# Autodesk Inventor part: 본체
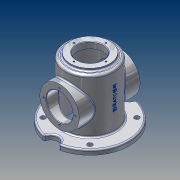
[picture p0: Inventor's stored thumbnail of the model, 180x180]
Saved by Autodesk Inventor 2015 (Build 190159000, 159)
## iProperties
Created: 2018-04
Part Number: 본체
Material: 알루미늄 6061
Document SubType Name: Modeling
Designer: user
Density: 2.7 g/cm^3
Appearance: 알루미늄 - 평지
Mass: 1147.05 g
Surface Area: 1200.36 cm^2
Volume: 424.833 cm^3
Author: user
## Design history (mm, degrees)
sketch "스케치1"
  geometry: L1 (0, 65)-(0, -60); L2 (-40, 65)-(-40, 60); L3 (-40, 60)-(-45, 60); L4 (-50, 55)-(-50, -47); L5 (-53, -50)-(-80, -50); L6 (-80, -50)-(-80, -60); L7 (-80, -60)-(-45, -60); L8 (-40, 65)-(-27, 65); L9 (-27, 65)-(-27, 52); L10 (-27, 52)-(-42, 52); L11 (-45, 49)-(-45, -60); A1 r 5 centre (-45, 55) between (-45, 60) and (-50, 55); A2 r 3 centre (-42, 49) between (-42, 52) and (-45, 49); A3 r 3 centre (-53, -47) between (-53, -50) and (-50, -47); 5 further points
  constraints: 22 end point, 7 perpendicular, 6 point on circle, 6 point on line, 6 tangent, 3 centre point, 2 horizontal alignment, 2 vertical, 1 horizontal, 1 midpoint, 1 vertical alignment
  dimensions: "d0" = 125 distance of L1.start L1.end; "d1" = 60 distance of point (0, 0) L1.end; "d2" = 54 diameter of L9 L1; "d3" = 80 diameter of L2 L1; "d4" = 10 distance between parallel lines of L7 L5; "d5" = 160 diameter of L6 L1; "d6" = 13 distance between parallel lines of L8 L10; "d7" = 110 distance between parallel lines of L5 L3; "d8" = 100 diameter of L4 L1; "d9" = 90 diameter of L11 L1; "d14" = 5 radius of A1; "d15" = 3 radius of A2; "d16" = 3 radius of A3
revolve "회전1" sketch "스케치1" stored, may be unused: angle "d10" = 90 deg
sketch "스케치2"
  geometry: C1 r 45 at (0, 0) reference; C2 r 80 at (0, 0) reference; C3 r 50 at (0, 0)
  constraints: 1 centre point, 1 coincident
  dimensions: "d11" = 100 diameter of C3
extrude "돌출1" join sketch "스케치2" distance "d12" = 8; taper "d13" = 0 deg
node "작업 평면1"
sketch "스케치3"
  geometry: C1 r 40 at (0, 0); C2 r 27 at (0, 0); 2 further points
  constraints: 2 centre point, 2 coincident, 1 vertical alignment
  dimensions: "d18" = 80 diameter of C1; "d19" = 54 diameter of C2; "d24" = 32.5 distance of point (0, 0) point (0, 32.5)
extrude "돌출2" join sketch "스케치3" stored distance "d20" = 8; taper "d21" = 0 deg
extrude "돌출3" cut sketch "스케치3" stored distance "d22" = 8; taper "d23" = 0 deg
hole "구멍1" sketch "스케치3" diameter "d25" = 3.242; stored, may be unused: countersink angle "d29" = 90 deg, drill point angle "d31" = 118 deg; dims "d26" = 8, "d27" = 4, "d28" = 2, "d30" = 10
sketch "스케치4"
  geometry: C1 r 40 at (0, 0) reference; 1 further point
  constraints: 1 vertical alignment
  dimensions: "d35" = 32.5 distance of C1.centre point (0, 32.5)
hole "구멍2" sketch "스케치4" at (0, 32.5) diameter "d36" = 3.242; stored, may be unused: countersink angle "d40" = 90 deg, drill point angle "d42" = 118 deg; dims "d37" = 8, "d38" = 4, "d39" = 2, "d41" = 10
sketch "스케치5" dims "d48" = 135
  geometry: L1 (0, 0)-(-99.526, 0); L2 (0, 0)-(-47.73, -47.73); C1 r 53 at (0, 0) reference; C2 r 15 at (0, -80); C3 r 15 at (0, 80); C4 r 5 at (-47.73, -47.73); A1 r 80 centre (0, 0) between (0, -80) and (0, 80) reference
  constraints: 4 end point, 3 centre point, 2 coincident, 2 point on circle, 2 vertical alignment, 1 horizontal, 3 other
  dimensions: "d46" = 30 diameter of C2; "d47" = 30 diameter of C3; "d49" = 45 deg angle of L1 L2; "d50" = 10 diameter of C4
extrude "돌출4" cut sketch "스케치5" stored distance "d51" = 8; taper "d52" = 0 deg
extrude "돌출5" cut sketch "스케치5" stored distance "d53" = 8; taper "d54" = 0 deg
fillet "모깎기1" dims "d58" = 3
chamfer "모따기1" distance "d59" = 1; stored, may be unused: second distance "d60" = 2, angle "d61" = 45 deg
fillet "모깎기2" dims "d62" = 3
fillet "모깎기3" dims "d63" = 3
node "작업 평면2"
sketch "스케치6"
  geometry: L1 (-64, -77.955)-(-64, 77.955) reference; 2 further points
  constraints: 1 horizontal alignment, 1 other
  dimensions: "d64" = 70 distance from line of L1 point (6, 0)
feature "엠보싱1" sketch "스케치6" dims "d0" = 125, "d1" = 60, "d2" = 54, "d3" = 80, "d4" = 10, "d5" = 160, "d6" = 13, "d7" = 110, "d8" = 100, "d9" = 90, "d14" = 5, "d15" = 3, "d16" = 3, "d65" = 0.5, "d66" = 0
node "솔리드1"
pattern_circular "원형 패턴1" dims angle "d33" = 360 deg
mirror "대칭1"
pattern_circular "원형 패턴2" dims angle "d44" = 360 deg
pattern_circular "원형 패턴3" dims angle "d56" = 360 deg
other parameters: "d17" = 62
